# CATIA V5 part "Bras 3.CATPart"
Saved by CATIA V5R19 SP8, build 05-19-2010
Part number: Bras 3
Bounding box of the stored display mesh (mm): x -225 to 225, y 1125 to 2775, z -825 to 675
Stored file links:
  C:\Users\ThinkMotion\Desktop\EU_thinkMotion\iao\IAO_MMS_Groupe3\fovide\fovide\Bras 3.CATPart
  C:\Users\ThinkMotion\Desktop\EU_thinkMotion\iao\IAO_MMS_Groupe3\fovide\fovide\fovide.CATProduct
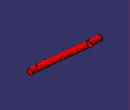
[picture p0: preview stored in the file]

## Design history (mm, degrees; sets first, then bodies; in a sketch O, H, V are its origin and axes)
External parameters (linked from other documents)
  `External.Rayon bielle` = 75 mm
  `External.Diamètre bielle` = 150 mm
Set1
  Plane1: linked copy from another document
  Line1: linked copy from another document
  Point1 "Point.A": linked copy from another document
  Point2 "Point.B": linked copy from another document
Body1 (main body)
  Sketch1 on Plane1, origin (0, 0, 0), H (0, 1, 0), V (0, 0, 1)
    point P1 (2700, 600)
    line L1 (2700, 600) -> (2750.1724, 544.2529)
    line L2 (2750.1724, 544.2529) -> (1250.1724, -805.7471)
    line L3 (1250.1724, -805.7471) -> (1200, -750)
    line L4 (1200, -750) -> (2700, 600)
    point P4 (1200, -750)
    reference projected line E1 (2700, 600) -> (1200, -750) from Line1
    reference projected point E2 (2700, 600) from Point1
    reference projected point E3 (1200, -750) from Point2
    length L1 = 75 {= `External.Rayon bielle`}
    parallelism: L4 E1, L4 L2, L1 L3
    coincidence: E2 P1, P4 E3
    perpendicularity: L1 L4
  Shaft1: profile Sketch1, axis Line1, angle 360
  Sketch2 on Plane1, origin (0, 0, 0), H (0, 1, 0), V (0, 0, 1)
    circle A1 centre (2700, 600) radius 75
    point P1 (2700, 600)
    reference projected point E1 (2700, 600) from Point1
    radius A1 = 75 {= `External.Rayon bielle`}
    coincidence: P1 E1
  Pad1: profile Sketch2, direction (1, 0, 0), length 75 {= `External.Rayon bielle`}, opposite side length 225 {= `External.Diamètre bielle` *1.5}
  Sketch3 on Plane1, origin (0, 0, 0), H (0, 1, 0), V (0, 0, 1)
    circle A1 centre (1200, -750) radius 75
    point P1 (1200, -750)
    reference projected point E1 (1200, -750) from Point2
    radius A1 = 75 {= `External.Rayon bielle`}
    coincidence: P1 E1
  Pad2: profile Sketch3, direction (1, 0, 0), length 225 {= `External.Diamètre bielle` *1.5}, mirrored extent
